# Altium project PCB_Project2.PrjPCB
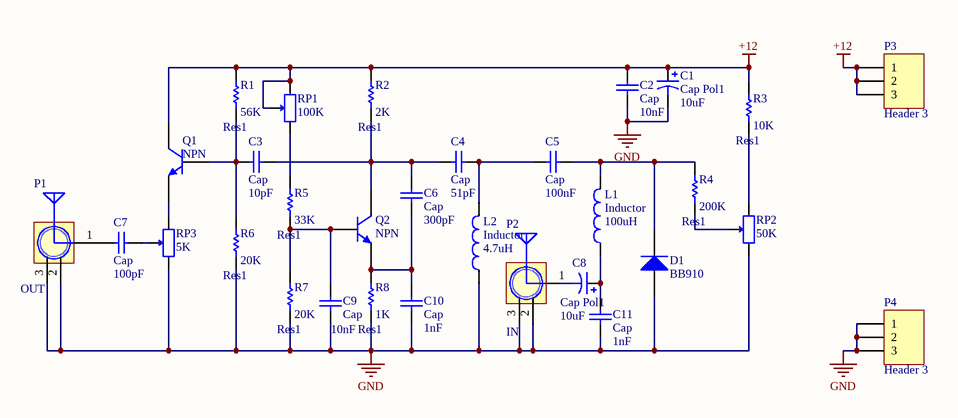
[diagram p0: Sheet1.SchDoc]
1 sheet, 31 parts. Net scope: global (net labels, ports and power ports of the same name join across sheets).
Board files: PCB1.PcbDoc, logo.PcbDoc

## Sheet Sheet1.SchDoc
size A4

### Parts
C1  Cap Pol1  value 10uF  [CAP 1.5*4*8]
C2  Cap  value 10nF  [C 0805_M]
C3  Cap  value 10pF  [C 0805_M]
C4  Cap  value 51pF  [C 0805_M]
C5  Cap  value 100nF  [C 0805_M]
C6  Cap  value 300pF  [C 0805_M]
C7  Cap  value 100pF  [C 0805_M]
C8  Cap Pol1  value 10uF  [CAP 1.5*4*8]
C9  Cap  value 10nF  [C 0805_M]
C10  Cap  value 1nF  [C 0805_M]
C11  Cap  value 1nF  [C 0805_M]
D1  BB910  [TO-226-AA]
L1  Inductor  value 100uH  [AL0204]
L2  Inductor  value 4.7uH  [AL0204]
P1  OUT  [SMA-KE]
P2  IN  [SMA-KE]
P3  Header 3  [HDR1X3]
P4  Header 3  [HDR1X3]
Q1  NPN  [TO-226-AA]
Q2  NPN  [TO-226-AA]
R1  Res1  value 56K  [C 0805_M]
R2  Res1  value 2K  [C 0805_M]
R3  Res1  value 10K  [C 0805_M]
R4  Res1  value 200K  [C 0805_M]
R5  Res1  value 33K  [C 0805_M]
R6  Res1  value 20K  [C 0805_M]
R7  Res1  value 20K  [C 0805_M]
R8  Res1  value 1K  [C 0805_M]
RP1  100K  [3296W]
RP2  50K  [3296W]
RP3  5K  [3296W]

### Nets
+12: C1.1 C2.2 P3.1 P3.2 P3.3 Q1.1(C) R1.2 R2.2 R3.2 RP1.1 RP1.2
GND: C1.2 C2.1 C9.1 C10.1 C11.1 D1.1(A) L2.1 P1.2(GND) P1.3(GND) P2.2(GND) P2.3(GND) P4.1 P4.2 P4.3 R6.1 R7.1 R8.1 RP2.3 RP3.1
NetC3_1: C3.1 Q1.2(B) R1.1 R6.2
NetC3_2: C3.2 C4.1 C6.2 Q2.1(C) R2.1
NetC4_2: C4.2 C5.1 L2.2
NetC5_2: C5.2 D1.2(K) L1.2 R4.2
NetC6_1: C6.1 C10.2 Q2.3(E) R8.2
NetC7_1: C7.1 P1.1(ANT)
NetC7_2: C7.2 RP3.2
NetC8_1: C8.1 C11.2 L1.1
NetC8_2: C8.2 P2.1(ANT)
NetC9_2: C9.2 Q2.2(B) R5.1 R7.2
NetQ1_3: Q1.3(E) RP3.3
NetR3_1: R3.1 RP2.1
NetR4_1: R4.1 RP2.2
NetR5_2: R5.2 RP1.3

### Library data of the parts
C1 C8 = Cap Pol1: Polarized Capacitor (Radial)
C2-C7 C9-C11 = Cap: Capacitor
D1 = Diode: Default Diode; pin to pad: 2>3
L1 L2 = Inductor: Code_IEC: 1005
P1 P2 = SMA: SMA-2.4G射频天线接口; 版权归属: 源创客
P3 P4 = Header 3: Header, 3-Pin
Q1 Q2 = NPN: NPN Bipolar Transistor
R1-R8 = Res1: Resistor
RP1-RP3 = RP-ID: 插件单联电位器; BOM名称: 插件电位器; 版权归属: 源创客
